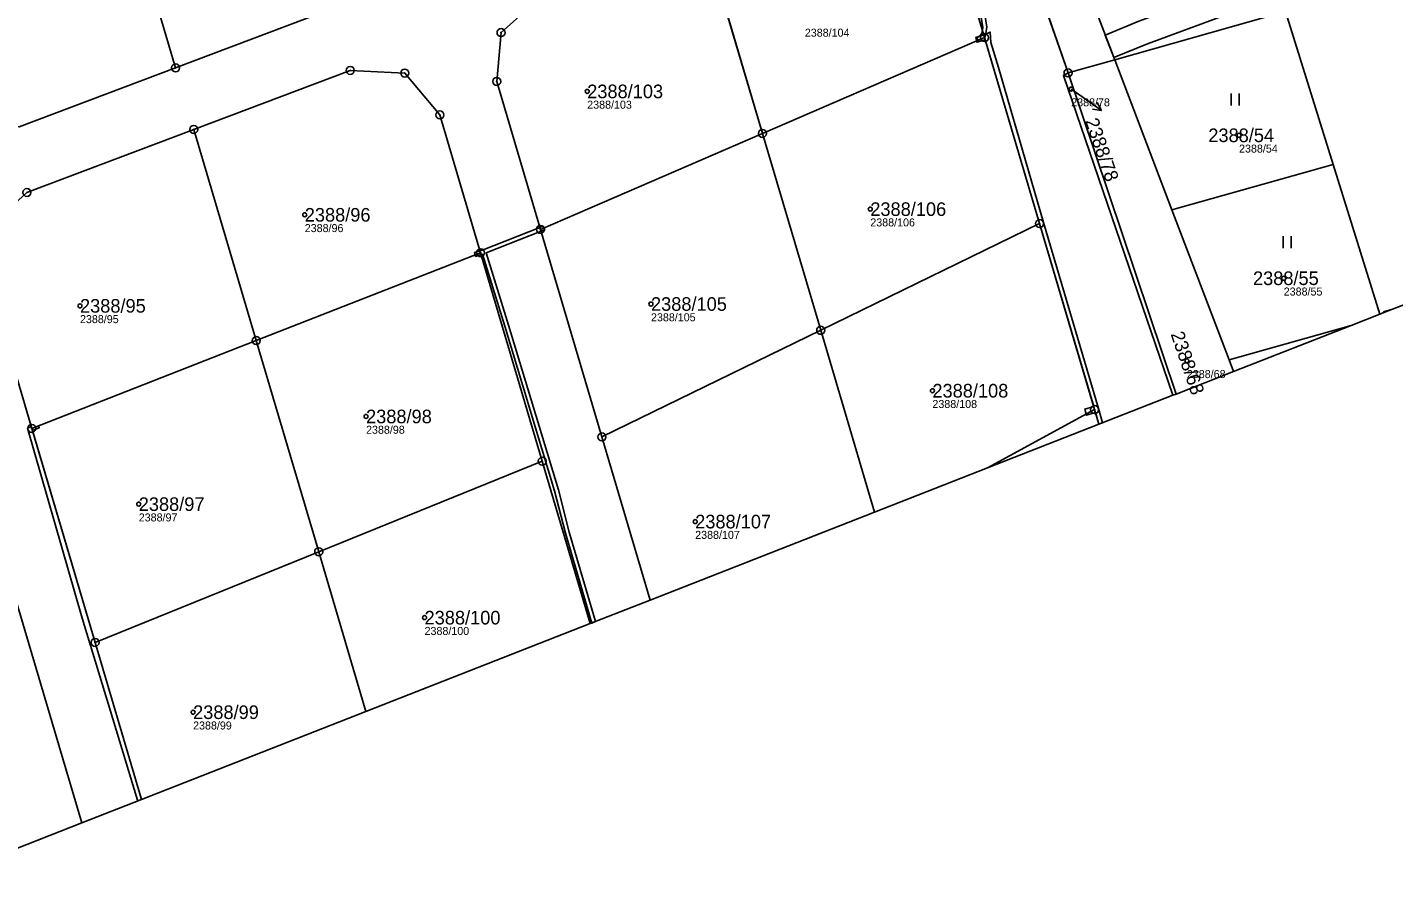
# Model space of a CAD drawing. Extents: x -758777 to -757896, y -1175225 to -1174486.
# Drawn here: x -758591.6 to -758420.9, y -1175224.9 to -1175119.6 of the extents above; entities that cross this region are included whole.
import ezdxf

# ---------------------------------------------------------------- set-up
doc = ezdxf.new("R2010")
doc.units = 0
for name, color, linetype in [('Definiční body', 7, 'Continuous'), ('Hranice parcel', 7, 'Continuous'), ('Parcelní čísla', 7, 'Continuous'), ('Polygon budovy', 7, 'Continuous'), ('Polygon parcely', 7, 'Continuous'), ('Pop  PČ popisy', 7, 'Continuous'), ('Věcná břemena k části', 7, 'Continuous'), ('Značky bodu BP', 7, 'Continuous'), ('Značky kultur', 7, 'Continuous')]:
    doc.layers.add(name, color=color, linetype=linetype)

msp = doc.modelspace()

# ---------------------------------------------------------------- linework, layer by layer
at = {"layer": 'Definiční body'}
for centre in [(-758521.64, -1175127.6), (-758461.17, -1175127.31), (-758440.2, -1175133.09), (-758556.93, -1175143.03), (-758486.27, -1175142.32), (-758434.62, -1175150.96), (-758513.67, -1175154.18), (-758585.01, -1175154.41), (-758446.72, -1175161.28), (-758478.51, -1175165.02), (-758549.27, -1175168.24), (-758577.67, -1175179.2), (-758508.15, -1175181.38), (-758541.96, -1175193.39), (-758570.88, -1175205.21)]:
    msp.add_circle(centre, 0.25, dxfattribs=at)
at = {"layer": 'Hranice parcel'}
for p, q in [((-758461.57, -1175125.29), (-758471.85, -1175095.62)), ((-758573.07, -1175124.66), (-758581.53, -1175096.02)), ((-758499.74, -1175132.86), (-758507.01, -1175108.26)), ((-758552.21, -1175116.78), (-758573.07, -1175124.66)), ((-758428.45, -1175136.72), (-758434.39, -1175117.61)), ((-758455.74, -1175123.64), (-758436.59, -1175118.23)), ((-758499.74, -1175132.86), (-758472, -1175120.88)), ((-758472, -1175120.88), (-758465.13, -1175144.13)), ((-758573.07, -1175124.66), (-758592.6, -1175132.04)), ((-758455.74, -1175123.64), (-758461.57, -1175125.29)), ((-758455.74, -1175123.64), (-758448.59, -1175142.41)), ((-758461.57, -1175125.29), (-758448.04, -1175165.43)), ((-758562.99, -1175158.76), (-758570.79, -1175132.36)), ((-758527.48, -1175144.85), (-758499.74, -1175132.86)), ((-758492.47, -1175157.47), (-758499.74, -1175132.86)), ((-758448.59, -1175142.41), (-758428.45, -1175136.72)), ((-758422.61, -1175155.46), (-758428.45, -1175136.72)), ((-758448.59, -1175142.41), (-758441.44, -1175161.17)), ((-758519.81, -1175170.8), (-758527.48, -1175144.85)), ((-758492.47, -1175157.47), (-758465.13, -1175144.13)), ((-758465.13, -1175144.13), (-758458.25, -1175167.38)), ((-758562.99, -1175158.76), (-758534.96, -1175147.77)), ((-758534.96, -1175147.77), (-758527.26, -1175173.83)), ((-758441.44, -1175161.17), (-758426.18, -1175156.86)), ((-758591.03, -1175169.74), (-758562.99, -1175158.76)), ((-758555.19, -1175185.16), (-758562.99, -1175158.76)), ((-758519.81, -1175170.8), (-758492.47, -1175157.47)), ((-758485.75, -1175180.21), (-758492.47, -1175157.47)), ((-758441.44, -1175161.17), (-758440.89, -1175162.62)), ((-758471.64, -1175174.68), (-758458.25, -1175167.38)), ((-758591.03, -1175169.74), (-758583.12, -1175196.49)), ((-758513.78, -1175191.2), (-758519.81, -1175170.8)), ((-758555.19, -1175185.16), (-758527.26, -1175173.83)), ((-758527.26, -1175173.83), (-758521.26, -1175194.13)), ((-758583.12, -1175196.49), (-758555.19, -1175185.16)), ((-758549.29, -1175205.12), (-758555.19, -1175185.16)), ((-758583.12, -1175196.49), (-758577.33, -1175216.11))]:
    msp.add_line(p, q, dxfattribs=at)
for points in [[(-758584.8, -1175219.04), (-758587.13, -1175211.17), (-758630.01, -1175066.05)], [(-758469.01, -1175094.99), (-758464.45, -1175100.79), (-758462.53, -1175105.82), (-758455.74, -1175123.64)], [(-758507.01, -1175108.26), (-758487.37, -1175100.84), (-758480.63, -1175101.18), (-758476.29, -1175106.35), (-758472, -1175120.88)], [(-758527.48, -1175144.85), (-758532.94, -1175126.36), (-758532.41, -1175120.25), (-758527.87, -1175116.14), (-758507.01, -1175108.26)], [(-758570.79, -1175132.36), (-758551.25, -1175124.97), (-758544.44, -1175125.31), (-758540.05, -1175130.54), (-758534.96, -1175147.77)], [(-758448.46, -1175165.59), (-758462.14, -1175125.6), (-758461.57, -1175125.29)], [(-758596, -1175144.18), (-758591.65, -1175140.24), (-758570.79, -1175132.36)], [(-758596, -1175144.18), (-758596.19, -1175144.35), (-758596.73, -1175150.46), (-758591.03, -1175169.74)], [(-758422.11, -1175155.26), (-758422.14, -1175155.17), (-758421.03, -1175154.84)], [(-758458.25, -1175167.38), (-758457.71, -1175169.22)]]:
    msp.add_lwpolyline(points, dxfattribs=at)
at = {"layer": 'Polygon budovy'}
msp.add_line((-758422.11, -1175155.26), (-758421.03, -1175154.84), dxfattribs=at)
msp.add_lwpolyline([(-758421.03, -1175154.84), (-758422.14, -1175155.17), (-758422.11, -1175155.26)], dxfattribs=at)
at = {"layer": 'Polygon parcely'}
for p, q in [((-758421.03, -1175154.84), (-758414.78, -1175152.39)), ((-758426.18, -1175156.86), (-758422.61, -1175155.46)), ((-758422.61, -1175155.46), (-758422.11, -1175155.26)), ((-758422.11, -1175155.26), (-758421.03, -1175154.84)), ((-758440.89, -1175162.62), (-758426.18, -1175156.86)), ((-758448.04, -1175165.43), (-758440.89, -1175162.62)), ((-758457.71, -1175169.22), (-758448.46, -1175165.59)), ((-758448.46, -1175165.59), (-758448.04, -1175165.43)), ((-758471.64, -1175174.68), (-758457.71, -1175169.22)), ((-758485.75, -1175180.21), (-758471.64, -1175174.68)), ((-758513.78, -1175191.2), (-758485.75, -1175180.21)), ((-758521.26, -1175194.13), (-758513.78, -1175191.2)), ((-758549.29, -1175205.12), (-758521.26, -1175194.13)), ((-758577.33, -1175216.11), (-758549.29, -1175205.12)), ((-758584.8, -1175219.04), (-758577.33, -1175216.11))]:
    msp.add_line(p, q, dxfattribs=at)
for points in [[(-758577.33, -1175216.11), (-758583.12, -1175196.49), (-758591.03, -1175169.74), (-758596.73, -1175150.46), (-758596.19, -1175144.35), (-758596, -1175144.18), (-758599.28, -1175131.71), (-758599.42, -1175131.7), (-758603.81, -1175126.47), (-758609.21, -1175108.24), (-758617.2, -1175081.18), (-758619.42, -1175073.66), (-758632.02, -1175040.71), (-758633.16, -1175038.79), (-758637.64, -1175040.23), (-758630.01, -1175066.05), (-758587.13, -1175211.17), (-758584.8, -1175219.04)], [(-758584.8, -1175219.04), (-758587.13, -1175211.17), (-758630.01, -1175066.05), (-758667.79, -1175076.66)], [(-758667.79, -1175076.66), (-758599.75, -1175224.9), (-758584.8, -1175219.04)], [(-758448.46, -1175165.59), (-758462.14, -1175125.6), (-758461.57, -1175125.29), (-758471.85, -1175095.62), (-758474.49, -1175088.01), (-758476.34, -1175080.74), (-758483.63, -1175082.55), (-758483.88, -1175088.57), (-758488.42, -1175092.69), (-758509.28, -1175100.57), (-758528.82, -1175107.95), (-758535.64, -1175107.61), (-758540.03, -1175102.38), (-758547.13, -1175106.57), (-758547.67, -1175112.67), (-758552.21, -1175116.78), (-758573.07, -1175124.66), (-758592.6, -1175132.04)], [(-758513.78, -1175191.2), (-758519.81, -1175170.8), (-758527.48, -1175144.85), (-758532.94, -1175126.36), (-758532.41, -1175120.25), (-758527.87, -1175116.14), (-758507.01, -1175108.26), (-758487.37, -1175100.84), (-758480.63, -1175101.18), (-758476.29, -1175106.35), (-758472, -1175120.88), (-758465.13, -1175144.13), (-758458.25, -1175167.38), (-758457.71, -1175169.22)], [(-758402.5, -1175147.57), (-758413.52, -1175111.73), (-758415.92, -1175112.41), (-758422.18, -1175114.17), (-758434.39, -1175117.61), (-758428.45, -1175136.72), (-758422.61, -1175155.46)], [(-758440.89, -1175162.62), (-758441.44, -1175161.17), (-758448.59, -1175142.41), (-758455.74, -1175123.64), (-758461.57, -1175125.29), (-758448.04, -1175165.43)], [(-758591.65, -1175140.24), (-758570.79, -1175132.36), (-758551.25, -1175124.97), (-758544.44, -1175125.31), (-758540.05, -1175130.54), (-758534.96, -1175147.77), (-758527.26, -1175173.83), (-758521.26, -1175194.13)], [(-758448.04, -1175165.43), (-758461.57, -1175125.29), (-758462.14, -1175125.6), (-758448.46, -1175165.59)], [(-758422.61, -1175155.46), (-758428.45, -1175136.72), (-758448.59, -1175142.41), (-758441.44, -1175161.17), (-758426.18, -1175156.86)], [(-758471.64, -1175174.68), (-758458.25, -1175167.38), (-758465.13, -1175144.13), (-758492.47, -1175157.47), (-758485.75, -1175180.21)], [(-758421.03, -1175154.84), (-758422.14, -1175155.17), (-758422.11, -1175155.26)], [(-758422.11, -1175155.26), (-758422.14, -1175155.17), (-758421.03, -1175154.84)], [(-758426.18, -1175156.86), (-758441.44, -1175161.17), (-758440.89, -1175162.62)], [(-758485.75, -1175180.21), (-758492.47, -1175157.47), (-758519.81, -1175170.8), (-758513.78, -1175191.2)], [(-758457.71, -1175169.22), (-758458.25, -1175167.38), (-758471.64, -1175174.68)], [(-758521.26, -1175194.13), (-758527.26, -1175173.83), (-758555.19, -1175185.16), (-758549.29, -1175205.12)], [(-758549.29, -1175205.12), (-758555.19, -1175185.16), (-758583.12, -1175196.49), (-758577.33, -1175216.11)]]:
    msp.add_lwpolyline(points, dxfattribs=at)
for points in [[(-758553.86, -1175083.8), (-758581.53, -1175096.02), (-758573.07, -1175124.66), (-758552.21, -1175116.78), (-758547.67, -1175112.67), (-758547.13, -1175106.57)], [(-758470.38, -1175093.24), (-758469.01, -1175094.99), (-758464.45, -1175100.79), (-758462.53, -1175105.82), (-758455.74, -1175123.64), (-758436.59, -1175118.23), (-758442.14, -1175100.06), (-758445.89, -1175087.81)], [(-758471.85, -1175095.62), (-758461.57, -1175125.29), (-758455.74, -1175123.64), (-758462.53, -1175105.82), (-758464.45, -1175100.79), (-758469.01, -1175094.99)], [(-758603.81, -1175126.47), (-758599.42, -1175131.7), (-758599.28, -1175131.71), (-758592.6, -1175132.04), (-758573.07, -1175124.66), (-758581.53, -1175096.02), (-758609.21, -1175108.24)], [(-758472, -1175120.88), (-758476.29, -1175106.35), (-758480.63, -1175101.18), (-758487.37, -1175100.84), (-758507.01, -1175108.26), (-758499.74, -1175132.86)], [(-758499.74, -1175132.86), (-758507.01, -1175108.26), (-758527.87, -1175116.14), (-758532.41, -1175120.25), (-758532.94, -1175126.36), (-758527.48, -1175144.85)], [(-758428.45, -1175136.72), (-758434.39, -1175117.61), (-758436.59, -1175118.23), (-758455.74, -1175123.64), (-758448.59, -1175142.41)], [(-758492.47, -1175157.47), (-758465.13, -1175144.13), (-758472, -1175120.88), (-758499.74, -1175132.86)], [(-758534.96, -1175147.77), (-758540.05, -1175130.54), (-758544.44, -1175125.31), (-758551.25, -1175124.97), (-758570.79, -1175132.36), (-758562.99, -1175158.76)], [(-758591.03, -1175169.74), (-758562.99, -1175158.76), (-758570.79, -1175132.36), (-758591.65, -1175140.24), (-758596, -1175144.18), (-758596.19, -1175144.35), (-758596.73, -1175150.46)], [(-758492.47, -1175157.47), (-758499.74, -1175132.86), (-758527.48, -1175144.85), (-758519.81, -1175170.8)], [(-758555.19, -1175185.16), (-758527.26, -1175173.83), (-758534.96, -1175147.77), (-758562.99, -1175158.76)], [(-758555.19, -1175185.16), (-758562.99, -1175158.76), (-758591.03, -1175169.74), (-758583.12, -1175196.49)]]:
    msp.add_lwpolyline(points, close=True, dxfattribs=at)
at = {"layer": 'Pop  PČ popisy'}
for p, q in [((-758461.17, -1175127.31), (-758459.85, -1175128.25)), ((-758459.85, -1175128.25), (-758457.39, -1175129.97)), ((-758457.39, -1175129.97), (-758458.5, -1175129.81)), ((-758457.39, -1175129.97), (-758457.93, -1175128.99))]:
    msp.add_line(p, q, dxfattribs=at)
at = {"layer": 'Věcná břemena k části'}
for p, q in [((-758457.71, -1175169.22), (-758457.24, -1175169.03)), ((-758521.07, -1175194.06), (-758520.61, -1175193.87)), ((-758577.8, -1175216.29), (-758577.32, -1175216.11))]:
    msp.add_line(p, q, dxfattribs=at)
msp.add_lwpolyline([(-758456.92, -1175120.55), (-758455.85, -1175123.36), (-758451.64, -1175121.64), (-758437.17, -1175116.34), (-758416.98, -1175108.94), (-758417.89, -1175105.98), (-758438.06, -1175113.43), (-758452.72, -1175118.84)], close=True, dxfattribs=at)
for points in [[(-758472.41, -1175118.37), (-758472.21, -1175119.59), (-758472.27, -1175119.96), (-758472.33, -1175120.34), (-758472.95, -1175121.02), (-758472.75, -1175121.2), (-758472, -1175120.88), (-758471.87, -1175120.56), (-758471.71, -1175119.59), (-758471.93, -1175118.25)], [(-758457.24, -1175169.03), (-758457.77, -1175167.24), (-758464.65, -1175143.99), (-758470.26, -1175124.61), (-758471.23, -1175121.5), (-758471.28, -1175120.18), (-758472.1, -1175120.53), (-758473.1, -1175120.87), (-758472.98, -1175121.3), (-758472.94, -1175121.45), (-758471.91, -1175121.17), (-758465.13, -1175144.13), (-758458.36, -1175167), (-758459.47, -1175167.31), (-758459.3, -1175167.95), (-758459.26, -1175168.08), (-758458.14, -1175167.76), (-758457.71, -1175169.22)], [(-758520.61, -1175193.87), (-758523.89, -1175182.69), (-758525.24, -1175177.4), (-758531.46, -1175156.81), (-758534.25, -1175147.79), (-758527.41, -1175145.09), (-758526.95, -1175144.91), (-758527.05, -1175144.67), (-758527.14, -1175144.45), (-758527.55, -1175144.61), (-758534.64, -1175147.4), (-758535.03, -1175147.53), (-758535.73, -1175147.76), (-758535.64, -1175148.04), (-758535.58, -1175148.23), (-758534.89, -1175148.01), (-758534.72, -1175147.96), (-758531.94, -1175156.95), (-758525.72, -1175177.54), (-758524.37, -1175182.83), (-758521.07, -1175194.06)], [(-758577.32, -1175216.11), (-758583.12, -1175196.49), (-758590.96, -1175169.98), (-758590.09, -1175169.64), (-758590.18, -1175169.41), (-758591.03, -1175169.74), (-758591.1, -1175169.5), (-758591.56, -1175169.72), (-758584.74, -1175193.45), (-758580.9, -1175206.04), (-758577.82, -1175216.22), (-758577.8, -1175216.29)]]:
    msp.add_lwpolyline(points, dxfattribs=at)
at = {"layer": 'Značky bodu BP'}
for centre, radius in [((-758532.41, -1175120.25), 0.5), ((-758532.41, -1175120.25), 0.0303), ((-758472, -1175120.88), 0.5), ((-758472, -1175120.88), 0.0303), ((-758573.07, -1175124.66), 0.5), ((-758573.07, -1175124.66), 0.0303), ((-758551.25, -1175124.97), 0.5), ((-758551.25, -1175124.97), 0.0303), ((-758544.44, -1175125.31), 0.5), ((-758461.57, -1175125.29), 0.5), ((-758544.44, -1175125.31), 0.0303), ((-758532.94, -1175126.36), 0.5), ((-758532.94, -1175126.36), 0.0303), ((-758461.57, -1175125.29), 0.0303), ((-758540.05, -1175130.54), 0.5), ((-758540.05, -1175130.54), 0.0303), ((-758570.79, -1175132.36), 0.5), ((-758570.79, -1175132.36), 0.0303), ((-758499.74, -1175132.86), 0.5), ((-758499.74, -1175132.86), 0.0303), ((-758591.65, -1175140.24), 0.5), ((-758465.13, -1175144.13), 0.5), ((-758527.48, -1175144.85), 0.5), ((-758527.48, -1175144.85), 0.0303), ((-758465.13, -1175144.13), 0.0303), ((-758534.96, -1175147.77), 0.5), ((-758534.96, -1175147.77), 0.0303), ((-758492.47, -1175157.47), 0.5), ((-758562.99, -1175158.76), 0.5), ((-758562.99, -1175158.76), 0.0303), ((-758492.47, -1175157.47), 0.0303), ((-758458.25, -1175167.38), 0.5), ((-758458.25, -1175167.38), 0.0303), ((-758591.03, -1175169.74), 0.5), ((-758591.03, -1175169.74), 0.0303), ((-758519.81, -1175170.8), 0.5), ((-758519.81, -1175170.8), 0.0303), ((-758527.26, -1175173.83), 0.5), ((-758527.26, -1175173.83), 0.0303), ((-758555.19, -1175185.16), 0.5), ((-758555.19, -1175185.16), 0.0303), ((-758583.12, -1175196.49), 0.5), ((-758583.12, -1175196.49), 0.0303)]:
    msp.add_circle(centre, radius, dxfattribs=at)
at = {"layer": 'Značky kultur'}
for p, q in [((-758441.17, -1175129.38), (-758441.17, -1175127.88)), ((-758440.17, -1175129.38), (-758440.17, -1175127.88)), ((-758434.7, -1175147.2), (-758434.7, -1175145.7)), ((-758433.7, -1175147.2), (-758433.7, -1175145.7))]:
    msp.add_line(p, q, dxfattribs=at)

# ---------------------------------------------------------------- texts
at = {"layer": 'Definiční body'}
for s, p in [('2388/104', (-758494.45, -1175120.76)), ('2388/103', (-758521.64, -1175129.76)), ('2388/78', (-758461.17, -1175129.47)), ('2388/54', (-758440.2, -1175135.25)), ('2388/106', (-758486.27, -1175144.48)), ('2388/96', (-758556.93, -1175145.19)), ('2388/55', (-758434.62, -1175153.12)), ('2388/95', (-758585.01, -1175156.57)), ('2388/105', (-758513.67, -1175156.34)), ('2388/68', (-758446.72, -1175163.44)), ('2388/108', (-758478.51, -1175167.18)), ('2388/98', (-758549.27, -1175170.4)), ('2388/97', (-758577.67, -1175181.36)), ('2388/107', (-758508.15, -1175183.54)), ('2388/100', (-758541.96, -1175195.55)), ('2388/99', (-758570.88, -1175207.37))]:
    msp.add_text(s, height=1, dxfattribs=at).set_placement(p)
at = {"layer": 'Parcelní čísla'}
for s, p in [('2388/103', (-758521.64, -1175128.45)), ('2388/54', (-758444.04, -1175133.94)), ('2388/106', (-758486.27, -1175143.17)), ('2388/96', (-758556.93, -1175143.88)), ('2388/55', (-758438.46, -1175151.81)), ('2388/95', (-758585.01, -1175155.26)), ('2388/105', (-758513.67, -1175155.03)), ('2388/108', (-758478.51, -1175165.87)), ('2388/98', (-758549.27, -1175169.09)), ('2388/97', (-758577.67, -1175180.05)), ('2388/107', (-758508.15, -1175182.23)), ('2388/100', (-758541.96, -1175194.24)), ('2388/99', (-758570.88, -1175206.06))]:
    msp.add_text(s, height=1.7, dxfattribs=at).set_placement(p)
for s, p in [('2388/78', (-758459.46, -1175131.27)), ('2388/68', (-758448.77, -1175157.93))]:
    msp.add_text(s, height=1.7, rotation=289, dxfattribs=at).set_placement(p)

doc.saveas('drawing.dxf')
